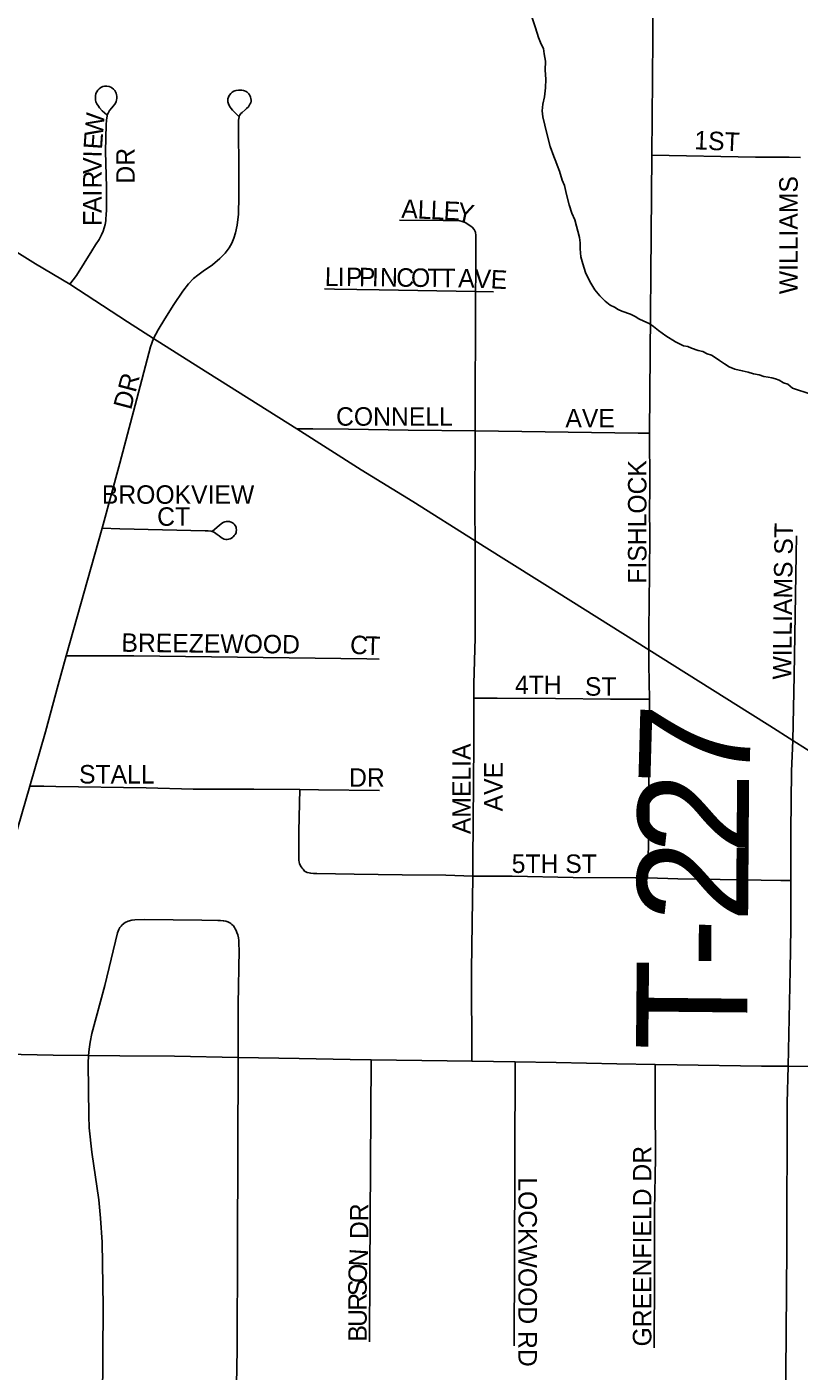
# Model space of a CAD drawing. Extents: x 0 to 68, y 0 to 52.9.
# Drawn here: x 55.901 to 56.946, y 49.64 to 51.458 of the extents above; entities that cross this region are included whole.
import ezdxf

# ---------------------------------------------------------------- set-up
doc = ezdxf.new("R2010")
doc.units = 0
for name, color, linetype in [('Default', 7, 'Continuous'), ('GM_X_County_Road', 7, 'Continuous'), ('GM_X_Minor_River', 7, 'Continuous'), ('GM_X_State_Route', 7, 'Continuous'), ('GM_X_Township_Road', 7, 'Continuous'), ('GM_X_Township_Road_Text', 7, 'Continuous'), ('GM_X_Township_Subdivision', 7, 'Continuous'), ('GM_X_Township_Subdivision_Text', 7, 'Continuous')]:
    doc.layers.add(name, color=color, linetype=linetype)

msp = doc.modelspace()

# ---------------------------------------------------------------- linework, layer by layer
at = {"layer": 'Default'}
for points in [[(56.7466, 51.2846), (56.7474, 51.3873), (56.7483, 51.5015), (56.7482, 51.5422), (56.749, 51.6388)], [(55.9593, 51.1098), (55.9682, 51.1217), (55.9892, 51.1551), (55.9939, 51.163), (55.9988, 51.1706), (56.0019, 51.1765), (56.0042, 51.1815), (56.0058, 51.1862), (56.0069, 51.1905), (56.0077, 51.1955), (56.0081, 51.1989), (56.0082, 51.2035), (56.0086, 51.2112), (56.0089, 51.2406), (56.0076, 51.2897), (56.0083, 51.3257), (56.0087, 51.332), (56.0096, 51.3379), (56.0102, 51.34), (56.0109, 51.3414), (56.0118, 51.343), (56.013, 51.3449), (56.016, 51.3485), (56.0178, 51.3506), (56.0199, 51.3534), (56.0209, 51.355), (56.0219, 51.357), (56.0225, 51.359), (56.0228, 51.3614), (56.0228, 51.3641), (56.0225, 51.366), (56.0219, 51.3684), (56.0212, 51.3701), (56.0199, 51.3721), (56.0183, 51.3738), (56.0161, 51.3756), (56.0145, 51.3766), (56.0123, 51.3774), (56.0093, 51.3779), (56.0063, 51.3778), (56.0037, 51.3772), (56.0011, 51.3761), (55.9988, 51.3743), (55.997, 51.3725), (55.9956, 51.3703), (55.9946, 51.3678), (55.994, 51.3649), (55.9938, 51.3633), (55.9938, 51.3614), (55.994, 51.3595), (55.9946, 51.3568), (55.9959, 51.3541), (55.9979, 51.3506), (55.9995, 51.3484), (56.0031, 51.3445), (56.0092, 51.3392)], [(56.0725, 51.0363), (56.0788, 51.0483), (56.0879, 51.063), (56.1, 51.0825), (56.1122, 51.1006), (56.1197, 51.1106), (56.1263, 51.1176), (56.1325, 51.1221), (56.1394, 51.1275), (56.1523, 51.1362), (56.1623, 51.1448), (56.1695, 51.1521), (56.1746, 51.1592), (56.1782, 51.1655), (56.181, 51.1722), (56.1832, 51.1795), (56.1855, 51.1897), (56.1872, 51.2049), (56.188, 51.2287), (56.1879, 51.2585), (56.1872, 51.328), (56.1874, 51.3318), (56.1877, 51.3342), (56.1882, 51.3365), (56.1887, 51.338), (56.1896, 51.3395), (56.1906, 51.3407), (56.1925, 51.3424), (56.1962, 51.3456), (56.1984, 51.3475), (56.2009, 51.3501), (56.2029, 51.3533), (56.2039, 51.3553), (56.2043, 51.3576), (56.2044, 51.359), (56.2042, 51.361), (56.2038, 51.3628), (56.2032, 51.3645), (56.2022, 51.3662), (56.2012, 51.3674), (56.1992, 51.3695), (56.1979, 51.3704), (56.1956, 51.3715), (56.1939, 51.372), (56.192, 51.3723), (56.1896, 51.3725), (56.1872, 51.3724), (56.1841, 51.372), (56.1825, 51.3715), (56.1809, 51.3709), (56.1787, 51.3696), (56.1769, 51.3679), (56.1751, 51.3658), (56.1743, 51.3644), (56.1738, 51.3631), (56.1731, 51.3606), (56.1729, 51.3587), (56.1731, 51.3565), (56.1738, 51.3539), (56.1747, 51.3517), (56.1763, 51.3493), (56.1775, 51.3475), (56.1794, 51.3453), (56.1872, 51.3373)], [(56.7431, 50.9083), (56.7466, 51.2846)], [(56.7466, 51.2846), (56.8868, 51.2817), (56.9322, 51.2817), (56.9473, 51.2813)], [(56.4053, 51.1964), (56.4643, 51.1963), (56.4834, 51.196), (56.4867, 51.1957), (56.4899, 51.1949), (56.4938, 51.1934), (56.5001, 51.1894)], [(56.5079, 51.1), (56.5085, 51.1227), (56.5085, 51.1648), (56.5084, 51.1705), (56.5083, 51.1758), (56.5077, 51.1804), (56.5071, 51.1823), (56.5063, 51.1839), (56.5035, 51.1869), (56.5001, 51.1894)], [(56.3039, 51.1037), (56.3172, 51.1032), (56.3776, 51.1021), (56.5079, 51.1)], [(56.5074, 50.9115), (56.5079, 51.1)], [(56.5079, 51.1), (56.5321, 51.0996)], [(56.003, 50.7797), (56.0268, 50.8679), (56.0477, 50.9465), (56.0684, 51.0251), (56.0725, 51.0363)], [(56.2662, 50.9145), (56.2878, 50.9143), (56.3361, 50.9139), (56.417, 50.9124), (56.5074, 50.9115)], [(56.5074, 50.7629), (56.5068, 50.8032), (56.5074, 50.9115)], [(56.5074, 50.9115), (56.728, 50.9086), (56.7431, 50.9083)], [(56.7436, 50.8292), (56.7437, 50.8656), (56.7432, 50.882), (56.7431, 50.9083)], [(56.7424, 50.6153), (56.7424, 50.6446), (56.743, 50.6773), (56.7437, 50.7673), (56.7435, 50.8084), (56.7436, 50.8292)], [(56.003, 50.7797), (56.027, 50.7791), (56.1421, 50.7765), (56.1463, 50.7762), (56.1504, 50.7757), (56.153, 50.7749), (56.1548, 50.774), (56.1566, 50.7726), (56.1584, 50.7713), (56.1611, 50.7694), (56.164, 50.7673), (56.1661, 50.7661), (56.1681, 50.7652), (56.1701, 50.7648), (56.1719, 50.7647), (56.174, 50.765), (56.176, 50.7655), (56.178, 50.7665), (56.1796, 50.7676), (56.1807, 50.7688), (56.1817, 50.77), (56.1829, 50.7715), (56.1836, 50.7727), (56.1842, 50.7742), (56.1844, 50.7754), (56.1846, 50.7776), (56.1844, 50.7793), (56.184, 50.781), (56.1832, 50.7829), (56.1827, 50.7837), (56.1817, 50.7852), (56.1801, 50.7866), (56.1792, 50.7873), (56.1775, 50.7882), (56.1763, 50.7885), (56.175, 50.7888), (56.173, 50.7889), (56.1709, 50.7888), (56.169, 50.7885), (56.1675, 50.7879), (56.1656, 50.787), (56.1641, 50.786), (56.1612, 50.7835), (56.1524, 50.7757)], [(55.9544, 50.6074), (56.003, 50.7797)], [(56.5055, 50.55), (56.5056, 50.5692), (56.5073, 50.6314), (56.5074, 50.7629)], [(56.9373, 50.4925), (56.9389, 50.5806), (56.9418, 50.7443), (56.9421, 50.7695)], [(55.905, 50.431), (55.9264, 50.5045), (55.9434, 50.5679), (55.9544, 50.6074)], [(55.9544, 50.6074), (55.9725, 50.6074), (56.0458, 50.607), (56.3611, 50.6033), (56.3775, 50.6029)], [(56.7431, 50.5485), (56.7425, 50.5956), (56.7424, 50.6153)], [(56.5043, 50.3093), (56.5043, 50.3293), (56.5055, 50.4888), (56.5055, 50.55)], [(56.5055, 50.55), (56.5372, 50.5498), (56.6161, 50.5493), (56.6907, 50.5488), (56.7431, 50.5485)], [(56.7407, 50.3067), (56.7411, 50.3251), (56.7418, 50.3497), (56.7431, 50.5485)], [(55.8063, 50.0695), (55.8075, 50.0767), (55.8113, 50.0909), (55.8602, 50.27), (55.8776, 50.3357), (55.905, 50.431)], [(55.905, 50.431), (55.9239, 50.4307), (55.9403, 50.4304), (56.0625, 50.4288), (56.1259, 50.4267), (56.2082, 50.4267), (56.2703, 50.4262)], [(56.2703, 50.4262), (56.2688, 50.3701), (56.269, 50.3349), (56.269, 50.3308), (56.2693, 50.3283), (56.2699, 50.3263), (56.2707, 50.3241), (56.272, 50.3218), (56.2734, 50.32), (56.2747, 50.3184), (56.2759, 50.3171), (56.2768, 50.3161), (56.2784, 50.315), (56.2804, 50.3142), (56.283, 50.3136), (56.285, 50.3132), (56.289, 50.3129), (56.2933, 50.3126), (56.3439, 50.3119), (56.4087, 50.3109), (56.4677, 50.3103), (56.5043, 50.3093)], [(56.2703, 50.4262), (56.2956, 50.426), (56.3782, 50.4249)], [(56.5029, 50.0589), (56.5026, 50.182), (56.5043, 50.3093)], [(56.5043, 50.3093), (56.5577, 50.3091), (56.6399, 50.3073), (56.7243, 50.307), (56.7407, 50.3067)], [(56.7407, 50.3067), (56.7815, 50.3057), (56.8677, 50.3043), (56.9211, 50.3034), (56.9345, 50.3033)], [(55.9846, 50.0665), (55.9852, 50.075), (55.9866, 50.0848), (55.989, 50.0965), (56.0064, 50.1611), (56.0237, 50.2323), (56.0254, 50.2368), (56.0269, 50.2396), (56.0286, 50.2417), (56.0301, 50.2435)], [(56.1867, 50.064), (56.1869, 50.1356), (56.1881, 50.2095), (56.1879, 50.2166), (56.1877, 50.222), (56.1873, 50.2258), (56.1866, 50.2297), (56.1853, 50.2331), (56.1843, 50.2358), (56.183, 50.2381), (56.1821, 50.2399), (56.1805, 50.2418), (56.1784, 50.2438), (56.1769, 50.2449), (56.1756, 50.246), (56.1731, 50.2473), (56.1704, 50.2481), (56.1677, 50.2487), (56.1664, 50.2489), (56.1632, 50.2491), (56.1594, 50.2491), (56.1377, 50.2498), (56.0603, 50.2506), (56.047, 50.25), (56.043, 50.2495), (56.038, 50.2483), (56.034, 50.2465), (56.0301, 50.2435)], [(55.8063, 50.0695), (55.9368, 50.0672), (55.9846, 50.0665)], [(56.0035, 49.5968), (56.0044, 49.7272), (56.0029, 49.814), (56.0009, 49.8467), (55.9983, 49.8711), (55.989, 49.936), (55.9855, 49.9686), (55.9847, 49.985), (55.9841, 50.0563), (55.9846, 50.0665)], [(55.9846, 50.0665), (56.0269, 50.0659), (56.1007, 50.0656), (56.1867, 50.064)], [(56.1842, 49.597), (56.1854, 49.669), (56.186, 49.8085), (56.1867, 50.064)], [(56.1867, 50.064), (56.2694, 50.0625)]]:
    msp.add_lwpolyline(points, dxfattribs=at)
at = {"layer": 'GM_X_County_Road'}
for points in [[(56.2694, 50.0625), (56.3383, 50.0613), (56.3666, 50.0609)], [(56.3666, 50.0609), (56.4695, 50.0595), (56.5029, 50.0589)], [(56.5029, 50.0589), (56.5615, 50.0579)], [(56.5615, 50.0579), (56.617, 50.0569), (56.6989, 50.0554), (56.7511, 50.0546)], [(56.7511, 50.0546), (56.7809, 50.0541), (56.8947, 50.052), (56.9307, 50.052)], [(56.9307, 50.052), (57.0175, 50.0506), (57.0992, 50.0487), (57.279, 50.046), (57.4262, 50.0433), (57.5651, 50.0399), (57.5952, 50.0399), (57.6136, 50.04)]]:
    msp.add_lwpolyline(points, dxfattribs=at)
at = {"layer": 'GM_X_Minor_River'}
for points in [[(56.5845, 51.4701), (56.5893, 51.4569), (56.593, 51.4438), (56.5968, 51.4347), (56.5997, 51.4286), (56.6006, 51.4216), (56.6024, 51.4115), (56.6021, 51.3995), (56.6029, 51.3875), (56.6027, 51.3754), (56.6014, 51.3634), (56.5992, 51.3534), (56.598, 51.3444)], [(56.598, 51.3444), (56.5989, 51.3364), (56.6016, 51.3253), (56.6053, 51.3102), (56.6091, 51.2961), (56.6138, 51.2829), (56.6167, 51.2758), (56.6186, 51.2708), (56.6214, 51.2627), (56.6252, 51.2506), (56.6281, 51.2435), (56.6308, 51.2314), (56.6346, 51.2173), (56.6384, 51.2062), (56.6422, 51.1971), (56.6487, 51.1729), (56.6496, 51.1658), (56.6494, 51.1578), (56.6502, 51.1468), (56.653, 51.1377), (56.6568, 51.1256), (56.6626, 51.1134), (56.6694, 51.1023), (56.6762, 51.0941), (56.6831, 51.0869), (56.69, 51.0818), (56.696, 51.0787), (56.7009, 51.0755), (56.7059, 51.0734), (56.7178, 51.0692), (56.7238, 51.0661), (56.7288, 51.0629), (56.7357, 51.0598), (56.7427, 51.0566), (56.7486, 51.0525), (56.7555, 51.0474), (56.7654, 51.0401), (56.7783, 51.0319), (56.7892, 51.0266), (56.7952, 51.0255), (56.8002, 51.0234), (56.8092, 51.0202), (56.8152, 51.0191), (56.8211, 51.0159), (56.8271, 51.0138), (56.832, 51.0107), (56.838, 51.0066), (56.8449, 51.0024), (56.8509, 50.9983), (56.8588, 50.9951), (56.8688, 50.9929), (56.8768, 50.9908), (56.8838, 50.9886), (56.8918, 50.9874), (56.8977, 50.9853), (56.9037, 50.9842), (56.9087, 50.9831), (56.9137, 50.982), (56.9187, 50.9799), (56.9247, 50.9767), (56.9306, 50.9746), (56.9366, 50.9695), (56.9615, 50.961)]]:
    msp.add_lwpolyline(points, dxfattribs=at)
at = {"layer": 'GM_X_State_Route'}
for points in [[(55.3305, 51.5019), (55.4339, 51.4362), (55.4592, 51.4207), (55.4815, 51.4064), (55.6126, 51.3233), (55.6698, 51.2887), (55.8211, 51.1945), (55.913, 51.1373), (55.9593, 51.1098), (56.037, 51.0589), (56.0725, 51.0363), (56.1336, 50.9975), (56.2662, 50.9145), (56.3533, 50.859), (56.423, 50.8158), (56.5074, 50.7629), (56.5464, 50.7385), (56.6019, 50.7035), (56.7424, 50.6153), (56.8796, 50.5293), (56.906, 50.5124)], [(56.906, 50.5124), (56.9373, 50.4925), (56.9556, 50.4808), (57.0115, 50.4464), (57.0739, 50.4071), (57.1165, 50.3799), (57.2328, 50.3057), (57.402, 50.1964), (57.4669, 50.1545), (57.5009, 50.1318), (57.5273, 50.1125), (57.5591, 50.0868), (57.6136, 50.04), (57.6337, 50.0227), (57.6839, 49.9805)]]:
    msp.add_lwpolyline(points, dxfattribs=at)
at = {"layer": 'GM_X_Township_Road'}
for points in [[(56.9345, 50.3033), (56.9344, 50.3697), (56.9355, 50.4512), (56.9373, 50.4925)], [(56.9345, 50.2769), (56.9345, 50.3033)], [(56.9307, 50.052), (56.9334, 50.1821), (56.9345, 50.2392), (56.9345, 50.2769)], [(56.9268, 49.5105), (56.9272, 49.5845), (56.9282, 49.6912), (56.9291, 49.8057), (56.9297, 50.0024), (56.9307, 50.052)]]:
    msp.add_lwpolyline(points, dxfattribs=at)
at = {"layer": 'GM_X_Township_Subdivision'}
for points in [[(56.365, 49.7748), (56.3666, 50.0609)], [(56.5606, 49.7904), (56.5615, 50.0579)], [(56.7502, 49.777), (56.7501, 49.857), (56.7513, 49.9283), (56.751, 50.0036), (56.7511, 50.0366), (56.7511, 50.0546)], [(56.5602, 49.6739), (56.5606, 49.7904)], [(56.3645, 49.6794), (56.365, 49.7748)], [(56.7496, 49.6713), (56.7502, 49.7742), (56.7502, 49.777)]]:
    msp.add_lwpolyline(points, dxfattribs=at)

# ---------------------------------------------------------------- texts
at = {"layer": 'Default'}
for s, rotation, p in [('W', 85.0674, (56.0039, 51.3092)), ('1ST', 357.5117, (56.8035, 51.2925)), ('E', 85.8988, (56.0026, 51.2917)), ('V', 89.9703, (56.0022, 51.2592)), ('I', 88.0326, (56.0022, 51.281)), ('DR', 90, (56.0469, 51.246)), ('R', 89.9514, (56.0022, 51.2394)), ('WILLIAMS', 90, (56.9438, 51.0964)), ('I', 89.985, (56.0022, 51.2284)), ('A', 89.9563, (56.0022, 51.2064)), ('F', 89.9727, (56.0022, 51.1888)), ('A', 357.4203, (56.4073, 51.1998)), ('L', 357.4309, (56.4293, 51.1988)), ('L', 357.4309, (56.4469, 51.198)), ('E', 357.4036, (56.4644, 51.1972)), ('Y', 348.5572, (56.481, 51.1965)), ('L', 359.3716, (56.304, 51.1077)), ('I', 359.3609, (56.3215, 51.1075)), ('P', 359.3716, (56.3325, 51.1074)), ('P', 359.3679, (56.3501, 51.1072)), ('I', 359.3882, (56.3677, 51.107)), ('N', 359.3661, (56.3787, 51.1069)), ('C', 359.3648, (56.4007, 51.1066)), ('O', 359.3735, (56.4205, 51.1064)), ('T', 359.3716, (56.4425, 51.1062)), ('T', 359.3543, (56.4601, 51.106)), ('A', 359.1257, (56.4843, 51.1057)), ('V', 357.5513, (56.5061, 51.1054)), ('E', 357.0202, (56.528, 51.1044)), ('DR', 75.2542, (56.0419, 50.939)), ('CONNELL', 0, (56.3193, 50.9185)), ('AVE', 0, (56.6295, 50.9163)), ('FISHLOCK', 90, (56.7392, 50.7048)), ('BROOKVIEW', 0, (56.0025, 50.8129)), ('CT', 0, (56.0773, 50.7831)), ('WILLIAMS ST', 89.3488, (56.935, 50.575)), ('BREEZEWOOD', 359.4035, (56.0289, 50.6127)), ('C', 355.3815, (56.3374, 50.6105)), ('T', 358.3617, (56.3586, 50.6088)), ('4TH', 0, (56.5613, 50.5555)), ('ST', 0, (56.6559, 50.5533)), ('AMELIA', 90, (56.5016, 50.366)), ('AVE', 90, (56.5446, 50.3968)), ('STALL', 0, (55.9717, 50.4345)), ('DR', 0, (56.3369, 50.4301)), ('5TH ST', 0, (56.5569, 50.3135))]:
    msp.add_text(s, height=0.025, rotation=rotation, dxfattribs=at).set_placement(p)
at = {"layer": 'GM_X_Township_Road_Text'}
for s, rotation, p in [('7', 88.3916, (56.878, 50.4287)), ('2', 89.5103, (56.8772, 50.3378)), ('2', 89.5749, (56.8766, 50.2462)), ('-', 89.4672, (56.876, 50.1849)), ('T', 89.4311, (56.8749, 50.0728))]:
    msp.add_text(s, height=0.15, rotation=rotation, dxfattribs=at).set_placement(p)
at = {"layer": 'GM_X_Township_Subdivision_Text'}
for s, rotation, p in [('GREENFIELD DR', 90, (56.7458, 49.673)), ('LOCKWOOD RD', 270, (56.566, 49.9018)), ('DR', 90, (56.363, 49.8182)), ('N', 86.2164, (56.3613, 49.7803)), ('O', 88.6886, (56.3608, 49.7586)), ('S', 89.9453, (56.3608, 49.7412)), ('R', 89.9703, (56.3608, 49.7214)), ('U', 89.9563, (56.3608, 49.6994)), ('B', 89.9757, (56.3608, 49.6796))]:
    msp.add_text(s, height=0.025, rotation=rotation, dxfattribs=at).set_placement(p)

doc.saveas('drawing.dxf')
